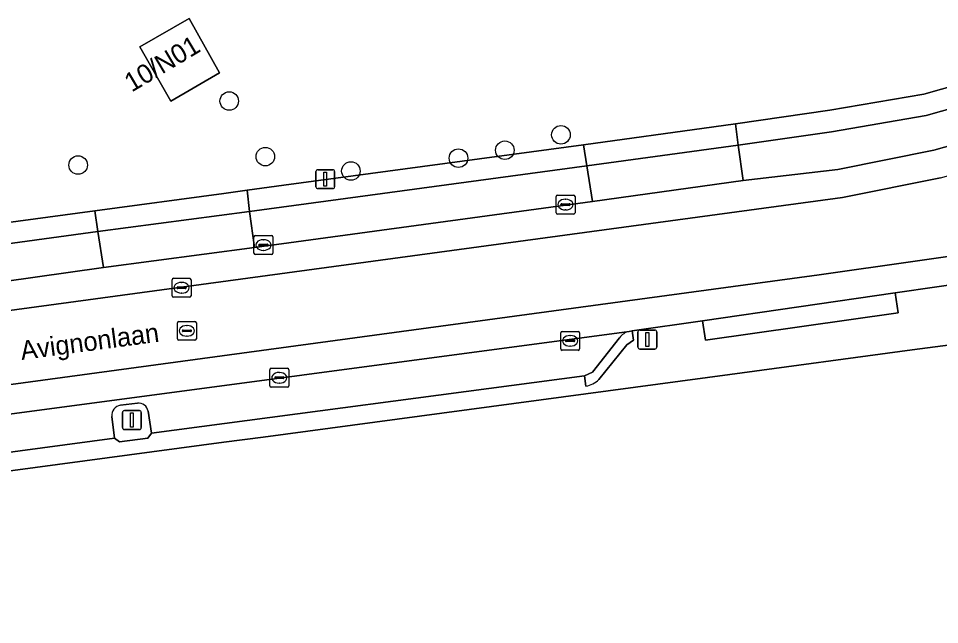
# Model space of a CAD drawing. Extents: x 158455 to 159797, y 387218 to 388672.
# Drawn here: x 158951.86 to 159000.45, y 387443.73 to 387475.71 of the extents above; entities that cross this region are included whole.
import ezdxf

# ---------------------------------------------------------------- set-up
doc = ezdxf.new("R2010")
doc.units = 0
for name, color, linetype in [('IMGEO_Boom', 7, 'Continuous'), ('IMGEO_Erf', 7, 'Continuous'), ('IMGEO_Kolk', 7, 'Continuous'), ('IMGEO_Lichtmast', 7, 'Continuous'), ('IMGEO_Openbare_ruimte_label', 7, 'Continuous'), ('IMGEO_Pand', 7, 'Continuous'), ('IMGEO_Pand_nummerreeks', 7, 'Continuous'), ('IMGEO_Parkeervlak_open', 7, 'Continuous'), ('IMGEO_Rijbaan_lokaal_gesloten', 7, 'Continuous'), ('IMGEO_Rioolput', 7, 'Continuous'), ('IMGEO_Voetpad_open', 7, 'Continuous')]:
    doc.layers.add(name, color=color, linetype=linetype)

msp = doc.modelspace()

# ---------------------------------------------------------------- linework, layer by layer
at = {"layer": 'IMGEO_Boom'}
for centre in [(158962.978, 387471.352), (158980.475, 387469.57), (158977.518, 387468.756), (158964.883, 387468.42), (158975.07, 387468.337), (158955.008, 387467.974), (158969.396, 387467.66)]:
    msp.add_circle(centre, 0.489, dxfattribs=at)
at = {"layer": 'IMGEO_Erf'}
msp.add_lwpolyline([(158962.469, 387472.84), (158959.903, 387471.348), (158958.261, 387474.212), (158960.868, 387475.711)], close=True, dxfattribs=at)
for points in [[(158897.588, 387457.682), (158930.651, 387462.152), (158938.394, 387463.195), (158955.888, 387465.567), (158962.696, 387466.48), (158963.921, 387466.644), (158965.858, 387466.905), (158981.668, 387469.041), (158988.546, 387469.989), (158989.691, 387470.147), (158994.651, 387470.867), (158999.62, 387471.71), (159006.133, 387473.558)], [(159004.113, 387458.902), (158999.01, 387458.217), (158989.379, 387456.925), (158973.012, 387454.73), (158964.768, 387453.624), (158962.694, 387453.346), (158918.158, 387447.372), (158913.387, 387446.696), (158913.533, 387445.59), (158900.447, 387443.729)]]:
    msp.add_lwpolyline(points, dxfattribs=at)
at = {"layer": 'IMGEO_Kolk'}
for p, q in [((158980.218, 387465.462), (158980.218, 387466.314)), ((158980.293, 387466.388), (158981.145, 387466.388)), ((158981.219, 387466.314), (158981.219, 387465.462)), ((158980.477, 387465.882), (158980.477, 387465.894)), ((158980.915, 387465.845), (158980.517, 387465.845)), ((158980.52, 387465.931), (158980.918, 387465.931)), ((158980.706, 387466.168), (158980.731, 387466.168)), ((158980.961, 387465.894), (158980.961, 387465.882)), ((158981.145, 387465.388), (158980.293, 387465.388)), ((158980.729, 387465.608), (158980.704, 387465.608)), ((158964.356, 387464.254), (158965.208, 387464.254)), ((158964.281, 387463.328), (158964.281, 387464.18)), ((158964.54, 387463.748), (158964.54, 387463.76)), ((158964.583, 387463.797), (158964.981, 387463.797)), ((158964.769, 387464.034), (158964.794, 387464.034)), ((158965.024, 387463.76), (158965.024, 387463.748)), ((158965.282, 387464.18), (158965.282, 387463.328)), ((158964.978, 387463.711), (158964.58, 387463.711)), ((158964.792, 387463.474), (158964.767, 387463.474)), ((158965.208, 387463.254), (158964.356, 387463.254)), ((158980.462, 387458.273), (158980.462, 387459.125)), ((158980.537, 387459.199), (158981.389, 387459.199)), ((158980.95, 387458.979), (158980.975, 387458.979)), ((158981.463, 387459.125), (158981.463, 387458.273)), ((158980.721, 387458.693), (158980.721, 387458.705)), ((158981.159, 387458.656), (158980.761, 387458.656)), ((158980.764, 387458.742), (158981.162, 387458.742)), ((158980.973, 387458.419), (158980.948, 387458.419)), ((158981.205, 387458.705), (158981.205, 387458.693)), ((158981.389, 387458.199), (158980.537, 387458.199)), ((158965.119, 387456.324), (158965.119, 387457.176)), ((158965.194, 387457.25), (158966.046, 387457.25)), ((158965.607, 387457.03), (158965.632, 387457.03)), ((158966.12, 387457.176), (158966.12, 387456.324)), ((158965.378, 387456.744), (158965.378, 387456.756)), ((158965.816, 387456.707), (158965.418, 387456.707)), ((158965.421, 387456.793), (158965.819, 387456.793)), ((158965.63, 387456.47), (158965.605, 387456.47)), ((158965.862, 387456.756), (158965.862, 387456.744)), ((158966.046, 387456.25), (158965.194, 387456.25))]:
    msp.add_line(p, q, dxfattribs=at)
for points in [[(158980.218, 387465.462), (158980.218, 387466.314)], [(158980.293, 387466.388), (158981.145, 387466.388)], [(158981.219, 387466.314), (158981.219, 387465.462)], [(158981.145, 387465.388), (158980.293, 387465.388)], [(158964.356, 387464.254), (158965.208, 387464.254)], [(158964.281, 387463.328), (158964.281, 387464.18)], [(158965.282, 387464.18), (158965.282, 387463.328)], [(158965.208, 387463.254), (158964.356, 387463.254)], [(158980.462, 387458.273), (158980.462, 387459.125)], [(158980.537, 387459.199), (158981.389, 387459.199)], [(158981.463, 387459.125), (158981.463, 387458.273)], [(158981.389, 387458.199), (158980.537, 387458.199)], [(158965.119, 387456.324), (158965.119, 387457.176)], [(158965.194, 387457.25), (158966.046, 387457.25)], [(158966.12, 387457.176), (158966.12, 387456.324)], [(158966.046, 387456.25), (158965.194, 387456.25)]]:
    msp.add_lwpolyline(points, dxfattribs=at)
for centre, radius, start, end in [((158980.295, 387466.312), 0.0765, 91.552, 178.448), ((158980.295, 387466.312), 0.0765, 91.552, 178.448), ((158981.143, 387466.312), 0.0765, 1.552, 88.448), ((158981.143, 387466.312), 0.0765, 1.552, 88.448), ((158980.517, 387465.891), 0.0403, 85.8775, 175.7526), ((158980.514, 387465.881), 0.0366, 178.938, 274.7102), ((158980.918, 387465.888), 0.043, 264.8664, 352.4533), ((158980.922, 387465.893), 0.0386, 1.7309, 96.639), ((158980.295, 387465.464), 0.0765, 181.552, 268.448), ((158980.295, 387465.464), 0.0765, 181.552, 268.448), ((158981.143, 387465.464), 0.0765, 271.552, 358.448), ((158981.143, 387465.464), 0.0765, 271.552, 358.448), ((158964.358, 387464.178), 0.0765, 91.552, 178.448), ((158964.358, 387464.178), 0.0765, 91.552, 178.448), ((158965.206, 387464.178), 0.0765, 1.552, 88.448), ((158965.206, 387464.178), 0.0765, 1.552, 88.448), ((158964.58, 387463.757), 0.0403, 85.8775, 175.7526), ((158964.577, 387463.747), 0.0366, 178.938, 274.7102), ((158964.981, 387463.754), 0.043, 264.8664, 352.4533), ((158964.985, 387463.759), 0.0386, 1.7309, 96.639), ((158964.358, 387463.33), 0.0765, 181.552, 268.448), ((158964.358, 387463.33), 0.0765, 181.552, 268.448), ((158965.206, 387463.33), 0.0765, 271.552, 358.448), ((158965.206, 387463.33), 0.0765, 271.552, 358.448), ((158980.539, 387459.123), 0.0765, 91.552, 178.448), ((158980.539, 387459.123), 0.0765, 91.552, 178.448), ((158981.387, 387459.123), 0.0765, 1.552, 88.448), ((158981.387, 387459.123), 0.0765, 1.552, 88.448), ((158980.761, 387458.702), 0.0403, 85.8775, 175.7526), ((158980.758, 387458.692), 0.0366, 178.938, 274.7102), ((158981.162, 387458.699), 0.043, 264.8664, 352.4533), ((158981.166, 387458.704), 0.0386, 1.7309, 96.639), ((158980.539, 387458.275), 0.0765, 181.552, 268.448), ((158980.539, 387458.275), 0.0765, 181.552, 268.448), ((158981.387, 387458.275), 0.0765, 271.552, 358.448), ((158981.387, 387458.275), 0.0765, 271.552, 358.448), ((158965.196, 387457.174), 0.0765, 91.552, 178.448), ((158965.196, 387457.174), 0.0765, 91.552, 178.448), ((158966.044, 387457.174), 0.0765, 1.552, 88.448), ((158966.044, 387457.174), 0.0765, 1.552, 88.448), ((158965.418, 387456.753), 0.0403, 85.8775, 175.7526), ((158965.415, 387456.743), 0.0366, 178.938, 274.7102), ((158965.819, 387456.75), 0.043, 264.8664, 352.4533), ((158965.823, 387456.755), 0.0386, 1.7309, 96.639), ((158965.196, 387456.326), 0.0765, 181.552, 268.448), ((158965.196, 387456.326), 0.0765, 181.552, 268.448), ((158966.044, 387456.326), 0.0765, 271.552, 358.448), ((158966.044, 387456.326), 0.0765, 271.552, 358.448)]:
    msp.add_arc(centre, radius, start, end, dxfattribs=at)
for centre, major_axis, ratio, start_param, end_param in [((158980.705, 387465.888), (-0.387, 0.002), 0.722429, 4.712389, 7.853982), ((158980.73, 387465.888), (-0.39, 0.002), 0.717154, 1.570796, 4.712389), ((158964.768, 387463.754), (-0.387, 0.002), 0.722429, 4.712389, 7.853982), ((158964.793, 387463.754), (-0.39, 0.002), 0.717154, 1.570796, 4.712389), ((158980.949, 387458.699), (-0.387, 0.002), 0.722429, 4.712389, 7.853982), ((158980.974, 387458.699), (-0.39, 0.002), 0.717154, 1.570796, 4.712389), ((158965.606, 387456.75), (-0.387, 0.002), 0.722429, 4.712389, 7.853982), ((158965.631, 387456.75), (-0.39, 0.002), 0.717154, 1.570796, 4.712389)]:
    msp.add_ellipse(centre, major_axis=major_axis, ratio=ratio, start_param=start_param, end_param=end_param, dxfattribs=at)
at = {"layer": 'IMGEO_Lichtmast'}
for p, q in [((158967.648, 387467.729), (158968.438, 387467.729)), ((158968.438, 387467.729), (158967.648, 387467.729)), ((158967.548, 387466.829), (158967.548, 387467.629)), ((158967.548, 387467.629), (158967.548, 387466.829)), ((158968.538, 387467.629), (158968.538, 387466.829)), ((158968.538, 387466.829), (158968.538, 387467.629)), ((158968.438, 387466.729), (158967.648, 387466.729)), ((158967.648, 387466.729), (158968.438, 387466.729)), ((158984.539, 387458.369), (158984.539, 387459.169)), ((158984.539, 387459.169), (158984.539, 387458.369)), ((158984.639, 387459.269), (158985.429, 387459.269)), ((158985.429, 387459.269), (158984.639, 387459.269)), ((158985.529, 387459.169), (158985.529, 387458.369)), ((158985.529, 387458.369), (158985.529, 387459.169)), ((158985.429, 387458.269), (158984.639, 387458.269)), ((158984.639, 387458.269), (158985.429, 387458.269)), ((158957.448, 387455.021), (158958.238, 387455.021)), ((158958.238, 387455.021), (158957.448, 387455.021)), ((158957.348, 387454.121), (158957.348, 387454.921)), ((158957.348, 387454.921), (158957.348, 387454.121)), ((158958.338, 387454.921), (158958.338, 387454.121)), ((158958.338, 387454.121), (158958.338, 387454.921)), ((158958.238, 387454.021), (158957.448, 387454.021)), ((158957.448, 387454.021), (158958.238, 387454.021))]:
    msp.add_line(p, q, dxfattribs=at)
for points in [[(158967.968, 387467.604), (158968.118, 387467.604), (158968.118, 387466.854), (158967.968, 387466.854), (158967.968, 387467.604)], [(158984.959, 387459.144), (158985.109, 387459.144), (158985.109, 387458.394), (158984.959, 387458.394), (158984.959, 387459.144)], [(158957.768, 387454.896), (158957.918, 387454.896), (158957.918, 387454.146), (158957.768, 387454.146), (158957.768, 387454.896)]]:
    msp.add_lwpolyline(points, dxfattribs=at)
for centre, start, end in [((158967.648, 387467.629), 90, 180), ((158967.648, 387467.629), 90, 180), ((158968.438, 387467.629), 0, 90), ((158968.438, 387467.629), 360, 90), ((158967.648, 387466.829), 180, 270), ((158967.648, 387466.829), 180, 270), ((158968.438, 387466.829), 270, 0), ((158968.438, 387466.829), 270, 0), ((158984.639, 387459.169), 90, 180), ((158984.639, 387459.169), 90, 180), ((158985.429, 387459.169), 0, 90), ((158985.429, 387459.169), 360, 90), ((158984.639, 387458.369), 180, 270), ((158984.639, 387458.369), 180, 270), ((158985.429, 387458.369), 270, 0), ((158985.429, 387458.369), 270, 0), ((158957.448, 387454.921), 90, 180), ((158957.448, 387454.921), 90, 180), ((158958.238, 387454.921), 0, 90), ((158958.238, 387454.921), 360, 90), ((158957.448, 387454.121), 180, 270), ((158957.448, 387454.121), 180, 270), ((158958.238, 387454.121), 270, 0), ((158958.238, 387454.121), 270, 0)]:
    msp.add_arc(centre, 0.1, start, end, dxfattribs=at)
at = {"layer": 'IMGEO_Pand'}
msp.add_lwpolyline([(158959.903, 387471.348), (158962.469, 387472.84), (158960.868, 387475.711), (158958.261, 387474.212)], close=True, dxfattribs=at)
at = {"layer": 'IMGEO_Parkeervlak_open'}
for points in [[(158995.082, 387467.743), (159000.141, 387468.754), (159007.975, 387470.957), (159007.403, 387472.766), (159006.462, 387472.482), (158999.747, 387470.59), (158994.756, 387469.734), (158989.819, 387469.025), (158990.085, 387467.153)], [(158964.041, 387465.524), (158964.317, 387463.627), (158982.134, 387466.045), (158981.846, 387467.928)]]:
    msp.add_lwpolyline(points, close=True, dxfattribs=at)
for points in [[(158938.803, 387460.084), (158956.353, 387462.566), (158956.056, 387464.46), (158941.246, 387462.44)], [(158984.066, 387459.2), (158915, 387449.968)], [(158958.698, 387454.987), (158958.877, 387453.822), (158981.712, 387456.848), (158982.136, 387457.045), (158983.568, 387458.866)], [(158957.236, 387455.3), (158958.135, 387455.409)], [(158915.75, 387449.771), (158917.58, 387448.459), (158918.018, 387448.348), (158956.929, 387453.557), (158956.787, 387454.706)]]:
    msp.add_lwpolyline(points, dxfattribs=at)
for centre, radius, start, end in [((158984.265, 387458.365), 0.858, 103.3982, 144.3), ((158957.324, 387454.767), 0.54, 99.3433, 186.486), ((158958.193, 387454.899), 0.513, 9.8302, 96.4626)]:
    msp.add_arc(centre, radius, start, end, dxfattribs=at)
at = {"layer": 'IMGEO_Rijbaan_lokaal_gesloten'}
for points in [[(159007.975, 387470.957), (159000.141, 387468.754), (158995.082, 387467.743), (158990.085, 387467.153), (158982.134, 387466.045), (158964.317, 387463.627), (158956.353, 387462.566), (158938.803, 387460.084), (158931.027, 387459.048), (158911.727, 387456.43), (158911.961, 387454.948), (158995.33, 387466.262), (159000.491, 387467.294), (159008.396, 387469.517)], [(159000.491, 387467.294), (158995.33, 387466.262), (158911.961, 387454.948), (158911.727, 387456.43), (158904.755, 387455.484), (158897.945, 387454.534)], [(158994.092, 387462.187), (159004.35, 387463.642)], [(158898.93, 387447.778), (158907.04, 387448.873), (158912.798, 387449.665), (158912.567, 387451.122), (158994.092, 387462.187)]]:
    msp.add_lwpolyline(points, dxfattribs=at)
msp.add_lwpolyline([(159004.514, 387462.15), (159004.35, 387463.642), (158994.092, 387462.187), (158912.567, 387451.122), (158912.798, 387449.665), (158915, 387449.968), (158984.066, 387459.2), (158984.232, 387459.222), (158987.935, 387459.762), (158998.105, 387461.227), (159002.493, 387461.865)], close=True, dxfattribs=at)
at = {"layer": 'IMGEO_Rioolput'}
for p, q in [((158959.965, 387461.074), (158959.965, 387461.926)), ((158960.04, 387462), (158960.892, 387462)), ((158960.966, 387461.926), (158960.966, 387461.074)), ((158960.224, 387461.494), (158960.224, 387461.506)), ((158960.662, 387461.457), (158960.264, 387461.457)), ((158960.267, 387461.543), (158960.665, 387461.543)), ((158960.453, 387461.78), (158960.478, 387461.78)), ((158960.708, 387461.506), (158960.708, 387461.494)), ((158960.892, 387461), (158960.04, 387461)), ((158960.476, 387461.22), (158960.451, 387461.22)), ((158960.244, 387458.801), (158960.244, 387459.653)), ((158960.319, 387459.727), (158961.171, 387459.727)), ((158960.732, 387459.507), (158960.757, 387459.507)), ((158961.245, 387459.653), (158961.245, 387458.801)), ((158960.503, 387459.221), (158960.503, 387459.233)), ((158960.941, 387459.184), (158960.543, 387459.184)), ((158960.546, 387459.27), (158960.944, 387459.27)), ((158960.755, 387458.947), (158960.73, 387458.947)), ((158960.987, 387459.233), (158960.987, 387459.221)), ((158961.171, 387458.727), (158960.319, 387458.727))]:
    msp.add_line(p, q, dxfattribs=at)
for points in [[(158959.965, 387461.074), (158959.965, 387461.926)], [(158960.04, 387462), (158960.892, 387462)], [(158960.966, 387461.926), (158960.966, 387461.074)], [(158960.892, 387461), (158960.04, 387461)], [(158960.244, 387458.801), (158960.244, 387459.653)], [(158960.319, 387459.727), (158961.171, 387459.727)], [(158961.245, 387459.653), (158961.245, 387458.801)], [(158961.171, 387458.727), (158960.319, 387458.727)]]:
    msp.add_lwpolyline(points, dxfattribs=at)
for centre, radius, start, end in [((158960.042, 387461.924), 0.0765, 91.552, 178.448), ((158960.042, 387461.924), 0.0765, 91.552, 178.448), ((158960.89, 387461.924), 0.0765, 1.552, 88.448), ((158960.89, 387461.924), 0.0765, 1.552, 88.448), ((158960.264, 387461.503), 0.0403, 85.8775, 175.7526), ((158960.261, 387461.493), 0.0366, 178.938, 274.7102), ((158960.665, 387461.5), 0.043, 264.8664, 352.4533), ((158960.669, 387461.505), 0.0386, 1.7309, 96.639), ((158960.042, 387461.076), 0.0765, 181.552, 268.448), ((158960.042, 387461.076), 0.0765, 181.552, 268.448), ((158960.89, 387461.076), 0.0765, 271.552, 358.448), ((158960.89, 387461.076), 0.0765, 271.552, 358.448), ((158960.321, 387459.651), 0.0765, 91.552, 178.448), ((158960.321, 387459.651), 0.0765, 91.552, 178.448), ((158961.169, 387459.651), 0.0765, 1.552, 88.448), ((158961.169, 387459.651), 0.0765, 1.552, 88.448), ((158960.543, 387459.23), 0.0403, 85.8775, 175.7526), ((158960.54, 387459.22), 0.0366, 178.938, 274.7102), ((158960.944, 387459.227), 0.043, 264.8664, 352.4533), ((158960.948, 387459.232), 0.0386, 1.7309, 96.639), ((158960.321, 387458.803), 0.0765, 181.552, 268.448), ((158960.321, 387458.803), 0.0765, 181.552, 268.448), ((158961.169, 387458.803), 0.0765, 271.552, 358.448), ((158961.169, 387458.803), 0.0765, 271.552, 358.448)]:
    msp.add_arc(centre, radius, start, end, dxfattribs=at)
for centre, major_axis, ratio, start_param, end_param in [((158960.452, 387461.5), (-0.387, 0.002), 0.722429, 4.712389, 7.853982), ((158960.477, 387461.5), (-0.39, 0.002), 0.717154, 1.570796, 4.712389), ((158960.731, 387459.227), (-0.387, 0.002), 0.722429, 4.712389, 7.853982), ((158960.756, 387459.227), (-0.39, 0.002), 0.717154, 1.570796, 4.712389)]:
    msp.add_ellipse(centre, major_axis=major_axis, ratio=ratio, start_param=start_param, end_param=end_param, dxfattribs=at)
at = {"layer": 'IMGEO_Voetpad_open'}
for points in [[(158989.691, 387470.147), (158989.819, 387469.025), (158994.756, 387469.734), (158999.747, 387470.59), (159006.462, 387472.482), (159006.133, 387473.558), (158999.62, 387471.71), (158994.651, 387470.867)], [(158988.546, 387469.989), (158981.668, 387469.041), (158981.846, 387467.928), (158989.819, 387469.025), (158989.691, 387470.147)], [(158964.041, 387465.524), (158981.846, 387467.928), (158981.668, 387469.041), (158965.858, 387466.905), (158963.921, 387466.644)], [(158990.085, 387467.153), (158989.819, 387469.025), (158981.846, 387467.928), (158982.134, 387466.045)], [(158962.696, 387466.48), (158955.888, 387465.567), (158956.056, 387464.46), (158964.041, 387465.524), (158963.921, 387466.644)], [(158964.317, 387463.627), (158964.041, 387465.524), (158956.056, 387464.46), (158956.353, 387462.566)], [(158987.935, 387459.762), (158988.093, 387458.727), (158998.258, 387460.18), (158998.105, 387461.227)]]:
    msp.add_lwpolyline(points, close=True, dxfattribs=at)
for points in [[(158941.165, 387462.979), (158941.246, 387462.44), (158956.056, 387464.46), (158955.888, 387465.567), (158938.394, 387463.195), (158938.727, 387460.61), (158939.126, 387460.892), (158940.435, 387462.567)], [(159004.686, 387461.013), (159002.669, 387460.708), (159002.493, 387461.865), (158998.105, 387461.227), (158998.258, 387460.18), (158988.093, 387458.727), (158987.935, 387459.762), (158984.232, 387459.222), (158984.31, 387458.727), (158983.949, 387458.486), (158982.479, 387456.656)], [(158982.479, 387456.656), (158983.949, 387458.486), (158984.31, 387458.727), (158984.232, 387459.222), (158984.066, 387459.2)], [(158989.379, 387456.925), (158999.01, 387458.217), (159004.113, 387458.902)], [(158983.568, 387458.866), (158982.136, 387457.045), (158981.712, 387456.848), (158981.79, 387456.313)], [(158900.447, 387443.729), (158913.533, 387445.59), (158913.387, 387446.696), (158918.158, 387447.372), (158962.694, 387453.346), (158964.768, 387453.624), (158973.012, 387454.73), (158989.379, 387456.925)], [(158981.79, 387456.313), (158981.712, 387456.848), (158958.877, 387453.822), (158958.684, 387453.568), (158957.191, 387453.368), (158956.929, 387453.557), (158918.018, 387448.348), (158918.082, 387447.801)], [(158958.135, 387455.409), (158957.236, 387455.3)], [(158956.787, 387454.706), (158956.929, 387453.557), (158957.191, 387453.368), (158958.684, 387453.568), (158958.877, 387453.822), (158958.698, 387454.987)]]:
    msp.add_lwpolyline(points, dxfattribs=at)
for centre, radius, start, end in [((158984.265, 387458.365), 0.858, 103.3982, 144.3), ((158981.608, 387457.543), 1.244, 278.438, 314.4923), ((158981.608, 387457.543), 1.244, 278.438, 314.4923), ((158957.324, 387454.767), 0.54, 99.3433, 186.486), ((158958.193, 387454.899), 0.513, 9.8302, 96.4626)]:
    msp.add_arc(centre, radius, start, end, dxfattribs=at)

# ---------------------------------------------------------------- texts
at = {"layer": 'IMGEO_Openbare_ruimte_label'}
msp.add_text('Avignonlaan', height=1, rotation=7.5871, dxfattribs=at).set_placement((158952.03, 387457.687))
at = {"layer": 'IMGEO_Pand_nummerreeks'}
msp.add_text('10/N01', height=1, rotation=30.7932, dxfattribs=at).set_placement((158957.834, 387471.796))

doc.saveas('drawing.dxf')
